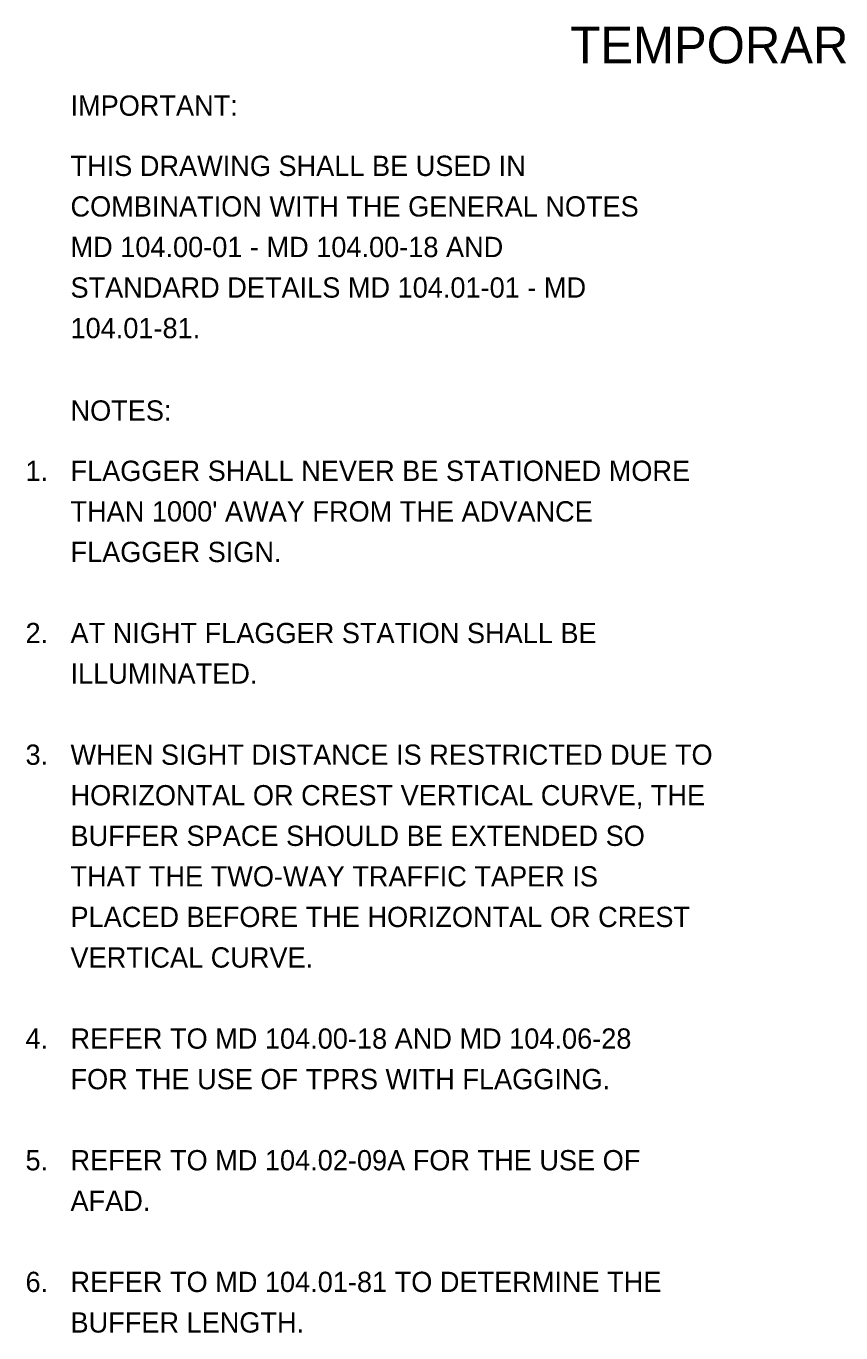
# Model space of a CAD drawing. Extents: x 1531.4 to 1538.6, y 1529.6 to 1539.7.
# Drawn here: x 1531.435 to 1533.844, y 1535.871 to 1539.738 of the extents above; entities that cross this region are included whole.
import ezdxf

# ---------------------------------------------------------------- set-up
doc = ezdxf.new("R2010")
doc.units = 0
doc.layers.add('DETL-NOTE', color=7, linetype='Continuous')
doc.layers.add('DETL-TITL', color=7, linetype='Continuous')

msp = doc.modelspace()

# ---------------------------------------------------------------- texts
at = {"layer": 'DETL-NOTE'}
for s, p in [('IMPORTANT:', (1531.5657, 1539.4726)), ('THIS DRAWING SHALL BE USED IN', (1531.5657, 1539.2943)), ('COMBINATION WITH THE GENERAL NOTES ', (1531.5657, 1539.1743)), ('MD 104.00-01 - MD 104.00-18 AND', (1531.5657, 1539.0543)), ('STANDARD DETAILS MD 104.01-01 - MD ', (1531.5657, 1538.9343)), ('104.01-81.', (1531.5657, 1538.8143)), ('NOTES:', (1531.5657, 1538.5703)), ('1.', (1531.4327, 1538.3919)), ('FLAGGER SHALL NEVER BE STATIONED MORE ', (1531.5657, 1538.3919)), ("THAN 1000' AWAY FROM THE ADVANCE ", (1531.5657, 1538.2719)), ('FLAGGER SIGN.', (1531.5657, 1538.1519)), ('2.', (1531.4327, 1537.9119)), ('AT NIGHT FLAGGER STATION SHALL BE ', (1531.5657, 1537.9119)), ('ILLUMINATED.', (1531.5657, 1537.7919)), ('3.', (1531.4327, 1537.5519)), ('WHEN SIGHT DISTANCE IS RESTRICTED DUE TO ', (1531.5657, 1537.5519)), ('HORIZONTAL OR CREST VERTICAL CURVE, THE ', (1531.5657, 1537.4319)), ('BUFFER SPACE SHOULD BE EXTENDED SO ', (1531.5657, 1537.3119)), ('THAT THE TWO-WAY TRAFFIC TAPER IS ', (1531.5657, 1537.1919)), ('PLACED BEFORE THE HORIZONTAL OR CREST ', (1531.5657, 1537.0719)), ('VERTICAL CURVE.', (1531.5657, 1536.9519)), ('4.', (1531.4327, 1536.7119)), ('REFER TO MD 104.00-18 AND MD 104.06-28 ', (1531.5657, 1536.7119)), ('FOR THE USE OF TPRS WITH FLAGGING.', (1531.5657, 1536.5919)), ('5.', (1531.4327, 1536.3519)), ('REFER TO MD 104.02-09A FOR THE USE OF ', (1531.5657, 1536.3519)), ('AFAD.', (1531.5657, 1536.2319)), ('6.', (1531.4327, 1535.9919)), ('REFER TO MD 104.01-81 TO DETERMINE THE ', (1531.5657, 1535.9919)), ('BUFFER LENGTH.', (1531.5657, 1535.8719))]:
    msp.add_text(s, height=0.06, dxfattribs=at).set_placement(p)
at = {"layer": 'DETL-TITL'}
msp.add_text('TEMPORARY TRAFFIC CONTROL TYPICAL APPLICATION', height=0.10852, dxfattribs=at).set_placement((1533.044, 1539.6276))

doc.saveas('drawing.dxf')
